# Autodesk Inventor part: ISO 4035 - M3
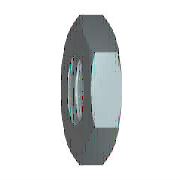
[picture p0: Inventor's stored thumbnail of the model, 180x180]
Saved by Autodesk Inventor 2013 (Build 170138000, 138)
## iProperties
IsCustomPart: 0
Created: 2012-02
Part Number: ISO 4035 - M3
Material: Edelstahl, 440C
Description: Sechskantmuttern, niedrige Form (mit Fase) - Produktklasse A und B
Document SubType Name: Modeling
Standard: ISO 4035
Designer: SteffenHaase
Standard Revision: Third edition 1999-08-15
Standards Organization: ISO
Language: de-DE
Size Designation: M3
Categories: <MemberInstance><Categories><Category DisplayName="Verbindungselemente" InternalName="e4da775c-781d-43d5-af7c-5136215cf5a6" Mnemonic="FSTN"><Category DisplayNam
Density: 7.75 g/cm^3
Author: SteffenHaase
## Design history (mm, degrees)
sketch "Skizze1"
  geometry: L1 (-3.175, 0)-(-1.588, 2.75); L2 (-1.588, 2.75)-(1.588, 2.75); L3 (1.588, 2.75)-(3.175, 0); L4 (3.175, 0)-(1.588, -2.75); L5 (1.588, -2.75)-(-1.588, -2.75); L6 (-1.588, -2.75)-(-3.175, 0); 2 further points
  constraints: 12 end point, 1 coincident, 1 horizontal, 11 other
  dimensions: "d0" = 6.35085 distance of L3.end L1.start (= 1.1547 x SW)
extrude "Körper" new body sketch "Skizze1" distance "d1" = 1.8 (= KOH); taper "d2" = 0 deg
sketch "Skizze2"
  geometry: L1 (0, 1.588)-(0, 3.175) reference; L2 (0, 3.175)-(1.8, 3.175) reference; L3 (1.8, 1.588)-(1.8, 3.175) reference; L4 (-0.36, 0)-(2.16, 0) reference; L5 (0.505, 3.175)-(0, 2.3); L6 (1.295, 3.175)-(1.8, 2.3)
  constraints: 4 end point, 4 point on line
  dimensions: "d3" = 30 deg angle of L1 L5 (= ANG1); "d4" = 30 deg angle of L3 L6 (= ANG2); "d5" = 4.6 diameter of L5.end L4 (= SW0); "d6" = 4.6 diameter of L6.end L4 (= SW01)
revolve "Fase1" sketch "Skizze2" stored, may be unused: angle "d7" = 90 deg
sketch "Skizze3"
  geometry: 4 further points
  constraints: 1 coincident, 1 other
hole "Gewinde" sketch "Skizze3" at (0, 0) diameter "d25" = 2.459; stored, may be unused: countersink angle "d29" = 82 deg, drill point angle "d31" = 118 deg; dims "d26" = 6, "d27" = 4, "d28" = 2, "d30" = 8
workaxis "Work Axis1"
workplane "Work Plane1"
body "Solid1"
chamfer "Fase2" distance "d8" = 0.27063 (= -0.5 x GD1 + 0.5 x NND); stored, may be unused: angle "d9" = 30 deg, second distance "d40" = 0.27063 (= -0.5 x GD1 + 0.5 x NND)
chamfer "Fase3" distance "d10" = 0.27063 (= -0.5 x GD1 + 0.5 x NND); stored, may be unused: angle "d11" = 30 deg, second distance "d41" = 0.27063 (= -0.5 x GD1 + 0.5 x NND)
other parameters: "ANG1" = 30 deg [user parameter; used in 1 equation term], "ANG2" = 30 deg [user parameter; used in 1 equation term], "NND" = 3 [user parameter; used in 4 equation terms], "KOH" = 1.8 [user parameter; used in 1 equation term], "SW" = 5.5 [user parameter; used in 2 equation terms], "SW0" = 4.6 [user parameter; used in 2 equation terms], "SW01" = 4.6 (= SW0) [user parameter; used in 1 equation term], "GD1" = 2.45873 (computed from THREADDIA, PTC, TOA) [user parameter; used in 4 equation terms], "d13" = 0, "d14" = 0, "d39" = 0, "d42" = 0, "GUL" = 0.27063 (= 0.541266 x PTC) [user parameter], "THREADDIA" = 3 [user parameter; used in 1 equation term], "TOA" = 30 deg [user parameter; used in 1 equation term], "PTC" = 0.5 [user parameter; used in 4 equation terms], "E0" = 6.3525 (= 1.155 x SW) [user parameter], "GAL" = 0.27063 (= 0.541266 x PTC) [user parameter]
